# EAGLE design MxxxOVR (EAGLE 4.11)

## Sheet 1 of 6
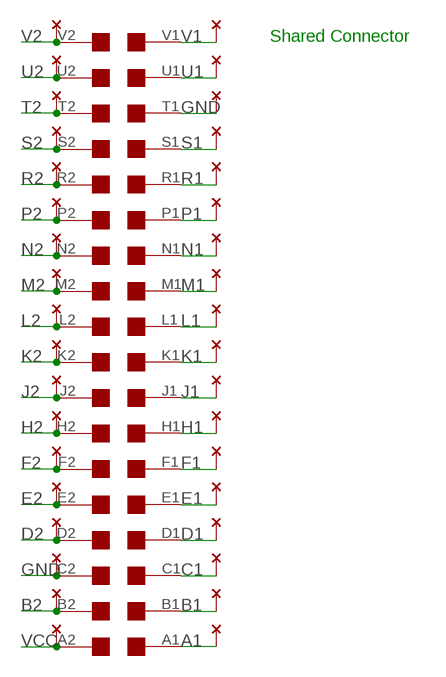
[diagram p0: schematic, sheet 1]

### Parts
U$1  EDGE-2  [EDGE-CON2]
U$4  THRU-HOLE2  [THRU-HOLEB]

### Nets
A1: U$1.A1 U$4.A2 ; also sheet 2,3,4,5,6
B1: U$1.B1 U$4.B2 ; also sheet 2,3,4,5,6
B2: U$1.B2 U$4.B1
C1: U$1.C1 U$4.C2 ; also sheet 2,3,4,5,6
D1: U$1.D1 U$4.D2 ; also sheet 2,3,4,5,6
D2: U$1.D2 U$4.D1 ; also sheet 2,3,4,5,6
E1: U$1.E1 U$4.E2 ; also sheet 2,3,4,5
E2: U$1.E2 U$4.E1 ; also sheet 2,3,4,5,6
F1: U$1.F1 U$4.F2 ; also sheet 2,3,4,5,6
F2: U$1.F2 U$4.F1 ; also sheet 2,3,4,5,6
GND [Power]: U$1.C2 U$1.T1 U$4.C1 U$4.T2 ; also sheet 2,3,4,5,6
H1: U$1.H1 U$4.H2 ; also sheet 2,3,4,5,6
H2: U$1.H2 U$4.H1 ; also sheet 2,3,4,5,6
J1: U$1.J1 U$4.J2 ; also sheet 2,3,4,5,6
J2: U$1.J2 U$4.J1 ; also sheet 2,3,4,5,6
K1: U$1.K1 U$4.K2 ; also sheet 2,3,4,5,6
K2: U$1.K2 U$4.K1 ; also sheet 2,3,4,5,6
L1: U$1.L1 U$4.L2 ; also sheet 2,3,4,5
L2: U$1.L2 U$4.L1 ; also sheet 2,3,4,5,6
M1: U$1.M1 U$4.M2 ; also sheet 2,3,4,5,6
M2: U$1.M2 U$4.M1 ; also sheet 2,3,4,5,6
N1: U$1.N1 U$4.N2 ; also sheet 2,3,4,5,6
N2: U$1.N2 U$4.N1 ; also sheet 2,3,4,5,6
P1: U$1.P1 U$4.P2 ; also sheet 2,3,4,5,6
P2: U$1.P2 U$4.P1 ; also sheet 2,3,4,5,6
R1: U$1.R1 U$4.R2 ; also sheet 2,3,4,5,6
R2: U$1.R2 U$4.R1 ; also sheet 2,3,4,5,6
S1: U$1.S1 U$4.S2 ; also sheet 2,3,4,5
S2: U$1.S2 U$4.S1 ; also sheet 2,3,4,5,6
T2: U$1.T2 U$4.T1 ; also sheet 2,3,4,5,6
U1: U$1.U1 U$4.U2 ; also sheet 2,3,4
U2: U$1.U2 U$4.U1 ; also sheet 2,3,4,5,6
V1: U$1.V1 U$4.V2 ; also sheet 2,3,4
V2: U$1.V2 U$4.V1 ; also sheet 2,3,4,5,6
VCC [Power]: U$1.A2 U$4.A1 ; also sheet 2,3,4,5,6

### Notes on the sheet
- Shared Connector

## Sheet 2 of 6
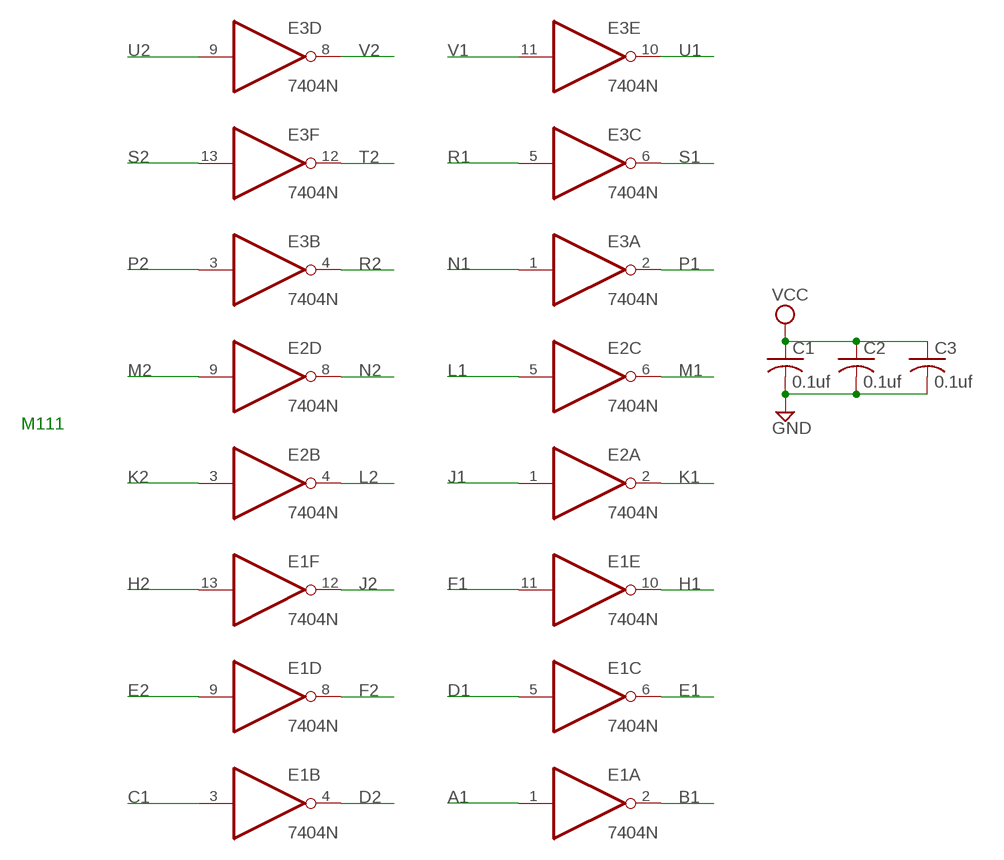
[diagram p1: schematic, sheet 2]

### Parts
C1  0.1uf  C-US050-025X075  [C050-025X075]
C2  0.1uf  C-US050-025X075  [C050-025X075]
C3  0.1uf  C-US050-025X075  [C050-025X075]
E1  7404N  [DIL14]
E2  7404N  [DIL14]
E3  7404N  [DIL14]

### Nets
A1: E1.1(A:I) ; also sheet 1,3,4,5,6
B1: E1.2(A:O) ; also sheet 1,3,4,5,6
C1: E1.3(B:I) ; also sheet 1,3,4,5,6
D1: E1.5(C:I) ; also sheet 1,3,4,5,6
D2: E1.4(B:O) ; also sheet 1,3,4,5,6
E1: E1.6(C:O) ; also sheet 1,3,4,5
E2: E1.9(D:I) ; also sheet 1,3,4,5,6
F1: E1.11(E:I) ; also sheet 1,3,4,5,6
F2: E1.8(D:O) ; also sheet 1,3,4,5,6
GND [Power]: C1.2 C2.2 C3.2 ; also sheet 1,3,4,5,6
H1: E1.10(E:O) ; also sheet 1,3,4,5,6
H2: E1.13(F:I) ; also sheet 1,3,4,5,6
J1: E2.1(A:I) ; also sheet 1,3,4,5,6
J2: E1.12(F:O) ; also sheet 1,3,4,5,6
K1: E2.2(A:O) ; also sheet 1,3,4,5,6
K2: E2.3(B:I) ; also sheet 1,3,4,5,6
L1: E2.5(C:I) ; also sheet 1,3,4,5
L2: E2.4(B:O) ; also sheet 1,3,4,5,6
M1: E2.6(C:O) ; also sheet 1,3,4,5,6
M2: E2.9(D:I) ; also sheet 1,3,4,5,6
N1: E3.1(A:I) ; also sheet 1,3,4,5,6
N2: E2.8(D:O) ; also sheet 1,3,4,5,6
P1: E3.2(A:O) ; also sheet 1,3,4,5,6
P2: E3.3(B:I) ; also sheet 1,3,4,5,6
R1: E3.5(C:I) ; also sheet 1,3,4,5,6
R2: E3.4(B:O) ; also sheet 1,3,4,5,6
S1: E3.6(C:O) ; also sheet 1,3,4,5
S2: E3.13(F:I) ; also sheet 1,3,4,5,6
T2: E3.12(F:O) ; also sheet 1,3,4,5,6
U1: E3.10(E:O) ; also sheet 1,3,4
U2: E3.9(D:I) ; also sheet 1,3,4,5,6
V1: E3.11(E:I) ; also sheet 1,3,4
V2: E3.8(D:O) ; also sheet 1,3,4,5,6
VCC [Power]: C1.1 C2.1 C3.1 ; also sheet 1,3,4,5,6
Unconnected: E2.10(E:O) E2.11(E:I) E2.12(F:O) E2.13(F:I)

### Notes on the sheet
- M111

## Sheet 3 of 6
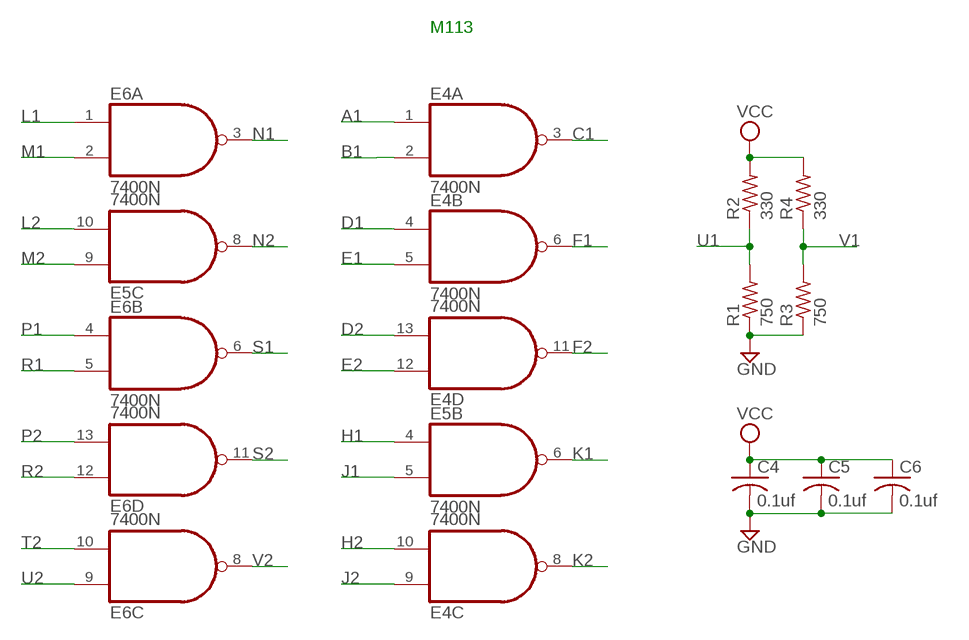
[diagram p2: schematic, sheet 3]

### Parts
C4  0.1uf  C-US050-025X075  [C050-025X075]
C5  0.1uf  C-US050-025X075  [C050-025X075]
C6  0.1uf  C-US050-025X075  [C050-025X075]
E4  7400N  [DIL14]
E5  7400N  [DIL14]
E6  7400N  [DIL14]
R1  750  R-US_0207/10  [0207/10]
R2  330  R-US_0207/10  [0207/10]
R3  750  R-US_0207/10  [0207/10]
R4  330  R-US_0207/10  [0207/10]

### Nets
A1: E4.1(A:I0) ; also sheet 1,2,4,5,6
B1: E4.2(A:I1) ; also sheet 1,2,4,5,6
C1: E4.3(A:O) ; also sheet 1,2,4,5,6
D1: E4.4(B:I0) ; also sheet 1,2,4,5,6
D2: E4.13(D:I1) ; also sheet 1,2,4,5,6
E1: E4.5(B:I1) ; also sheet 1,2,4,5
E2: E4.12(D:I0) ; also sheet 1,2,4,5,6
F1: E4.6(B:O) ; also sheet 1,2,4,5,6
F2: E4.11(D:O) ; also sheet 1,2,4,5,6
GND [Power]: C4.2 C5.2 C6.2 R1.1 R3.1 ; also sheet 1,2,4,5,6
H1: E5.4(B:I0) ; also sheet 1,2,4,5,6
H2: E4.10(C:I1) ; also sheet 1,2,4,5,6
J1: E5.5(B:I1) ; also sheet 1,2,4,5,6
J2: E4.9(C:I0) ; also sheet 1,2,4,5,6
K1: E5.6(B:O) ; also sheet 1,2,4,5,6
K2: E4.8(C:O) ; also sheet 1,2,4,5,6
L1: E6.1(A:I0) ; also sheet 1,2,4,5
L2: E5.10(C:I1) ; also sheet 1,2,4,5,6
M1: E6.2(A:I1) ; also sheet 1,2,4,5,6
M2: E5.9(C:I0) ; also sheet 1,2,4,5,6
N1: E6.3(A:O) ; also sheet 1,2,4,5,6
N2: E5.8(C:O) ; also sheet 1,2,4,5,6
P1: E6.4(B:I0) ; also sheet 1,2,4,5,6
P2: E6.13(D:I1) ; also sheet 1,2,4,5,6
R1: E6.5(B:I1) ; also sheet 1,2,4,5,6
R2: E6.12(D:I0) ; also sheet 1,2,4,5,6
S1: E6.6(B:O) ; also sheet 1,2,4,5
S2: E6.11(D:O) ; also sheet 1,2,4,5,6
T2: E6.10(C:I1) ; also sheet 1,2,4,5,6
U1: R1.2 R2.1 ; also sheet 1,2,4
U2: E6.9(C:I0) ; also sheet 1,2,4,5,6
V1: R3.2 R4.1 ; also sheet 1,2,4
V2: E6.8(C:O) ; also sheet 1,2,4,5,6
VCC [Power]: C4.1 C5.1 C6.1 R2.2 R4.2 ; also sheet 1,2,4,5,6
Unconnected: E5.1(A:I0) E5.2(A:I1) E5.3(A:O) E5.11(D:O) E5.12(D:I0) E5.13(D:I1)

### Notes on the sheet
- M113

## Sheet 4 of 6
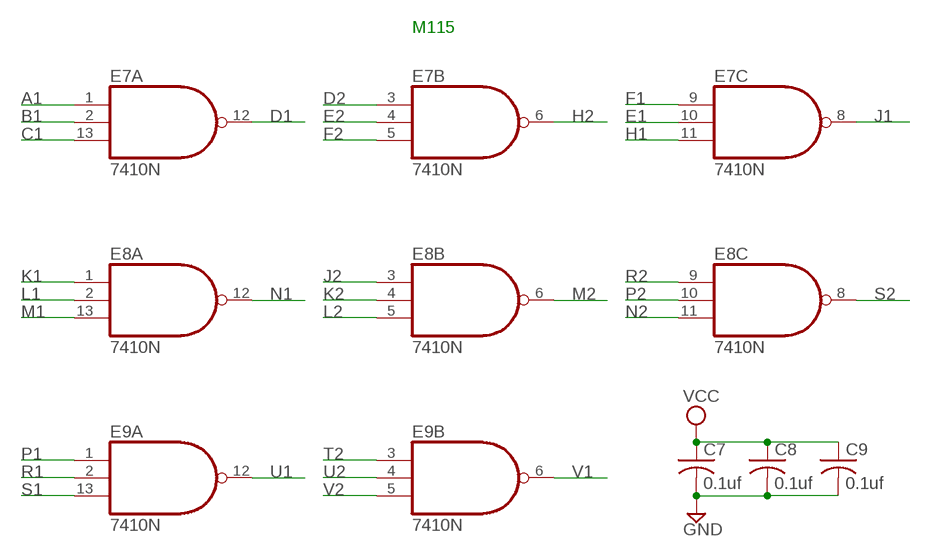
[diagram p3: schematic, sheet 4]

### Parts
C7  0.1uf  C-US050-025X075  [C050-025X075]
C8  0.1uf  C-US050-025X075  [C050-025X075]
C9  0.1uf  C-US050-025X075  [C050-025X075]
E7  7410N  [DIL14]
E8  7410N  [DIL14]
E9  7410N  [DIL14]

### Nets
A1: E7.1(A:I0) ; also sheet 1,2,3,5,6
B1: E7.2(A:I1) ; also sheet 1,2,3,5,6
C1: E7.13(A:I2) ; also sheet 1,2,3,5,6
D1: E7.12(A:O) ; also sheet 1,2,3,5,6
D2: E7.3(B:I0) ; also sheet 1,2,3,5,6
E1: E7.10(C:I1) ; also sheet 1,2,3,5
E2: E7.4(B:I1) ; also sheet 1,2,3,5,6
F1: E7.9(C:I0) ; also sheet 1,2,3,5,6
F2: E7.5(B:I2) ; also sheet 1,2,3,5,6
GND [Power]: C7.2 C8.2 C9.2 ; also sheet 1,2,3,5,6
H1: E7.11(C:I2) ; also sheet 1,2,3,5,6
H2: E7.6(B:O) ; also sheet 1,2,3,5,6
J1: E7.8(C:O) ; also sheet 1,2,3,5,6
J2: E8.3(B:I0) ; also sheet 1,2,3,5,6
K1: E8.1(A:I0) ; also sheet 1,2,3,5,6
K2: E8.4(B:I1) ; also sheet 1,2,3,5,6
L1: E8.2(A:I1) ; also sheet 1,2,3,5
L2: E8.5(B:I2) ; also sheet 1,2,3,5,6
M1: E8.13(A:I2) ; also sheet 1,2,3,5,6
M2: E8.6(B:O) ; also sheet 1,2,3,5,6
N1: E8.12(A:O) ; also sheet 1,2,3,5,6
N2: E8.11(C:I2) ; also sheet 1,2,3,5,6
P1: E9.1(A:I0) ; also sheet 1,2,3,5,6
P2: E8.10(C:I1) ; also sheet 1,2,3,5,6
R1: E9.2(A:I1) ; also sheet 1,2,3,5,6
R2: E8.9(C:I0) ; also sheet 1,2,3,5,6
S1: E9.13(A:I2) ; also sheet 1,2,3,5
S2: E8.8(C:O) ; also sheet 1,2,3,5,6
T2: E9.3(B:I0) ; also sheet 1,2,3,5,6
U1: E9.12(A:O) ; also sheet 1,2,3
U2: E9.4(B:I1) ; also sheet 1,2,3,5,6
V1: E9.6(B:O) ; also sheet 1,2,3
V2: E9.5(B:I2) ; also sheet 1,2,3,5,6
VCC [Power]: C7.1 C8.1 C9.1 ; also sheet 1,2,3,5,6
Unconnected: E9.8(C:O) E9.9(C:I0) E9.10(C:I1) E9.11(C:I2)

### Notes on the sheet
- M115

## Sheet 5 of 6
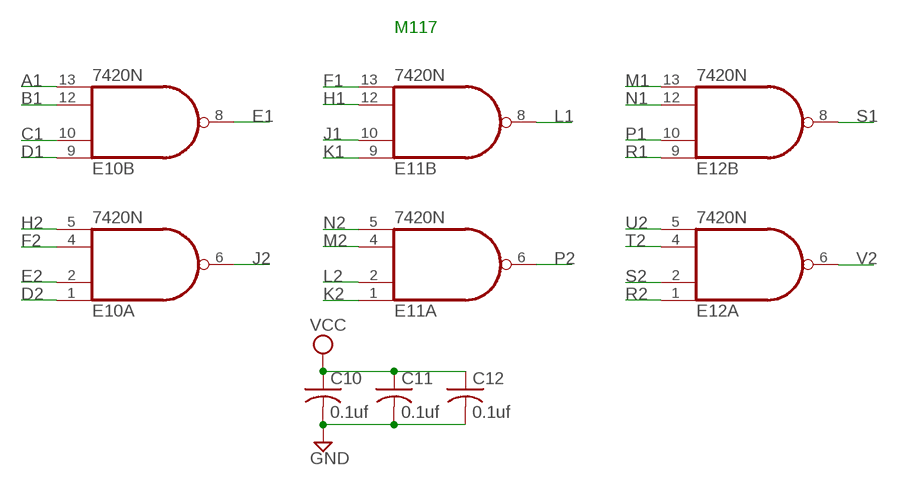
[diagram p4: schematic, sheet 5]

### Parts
C10  0.1uf  C-US050-025X075  [C050-025X075]
C11  0.1uf  C-US050-025X075  [C050-025X075]
C12  0.1uf  C-US050-025X075  [C050-025X075]
E10  7420N  74S20N  [DIL14]
E11  7420N  74S20N  [DIL14]
E12  7420N  74S20N  [DIL14]

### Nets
A1: E10.13(B:I3) ; also sheet 1,2,3,4,6
B1: E10.12(B:I2) ; also sheet 1,2,3,4,6
C1: E10.10(B:I1) ; also sheet 1,2,3,4,6
D1: E10.9(B:I0) ; also sheet 1,2,3,4,6
D2: E10.1(A:I0) ; also sheet 1,2,3,4,6
E1: E10.8(B:O) ; also sheet 1,2,3,4
E2: E10.2(A:I1) ; also sheet 1,2,3,4,6
F1: E11.13(B:I3) ; also sheet 1,2,3,4,6
F2: E10.4(A:I2) ; also sheet 1,2,3,4,6
GND [Power]: C10.2 C11.2 C12.2 ; also sheet 1,2,3,4,6
H1: E11.12(B:I2) ; also sheet 1,2,3,4,6
H2: E10.5(A:I3) ; also sheet 1,2,3,4,6
J1: E11.10(B:I1) ; also sheet 1,2,3,4,6
J2: E10.6(A:O) ; also sheet 1,2,3,4,6
K1: E11.9(B:I0) ; also sheet 1,2,3,4,6
K2: E11.1(A:I0) ; also sheet 1,2,3,4,6
L1: E11.8(B:O) ; also sheet 1,2,3,4
L2: E11.2(A:I1) ; also sheet 1,2,3,4,6
M1: E12.13(B:I3) ; also sheet 1,2,3,4,6
M2: E11.4(A:I2) ; also sheet 1,2,3,4,6
N1: E12.12(B:I2) ; also sheet 1,2,3,4,6
N2: E11.5(A:I3) ; also sheet 1,2,3,4,6
P1: E12.10(B:I1) ; also sheet 1,2,3,4,6
P2: E11.6(A:O) ; also sheet 1,2,3,4,6
R1: E12.9(B:I0) ; also sheet 1,2,3,4,6
R2: E12.1(A:I0) ; also sheet 1,2,3,4,6
S1: E12.8(B:O) ; also sheet 1,2,3,4
S2: E12.2(A:I1) ; also sheet 1,2,3,4,6
T2: E12.4(A:I2) ; also sheet 1,2,3,4,6
U2: E12.5(A:I3) ; also sheet 1,2,3,4,6
V2: E12.6(A:O) ; also sheet 1,2,3,4,6
VCC [Power]: C10.1 C11.1 C12.1 ; also sheet 1,2,3,4,6

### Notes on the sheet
- M117

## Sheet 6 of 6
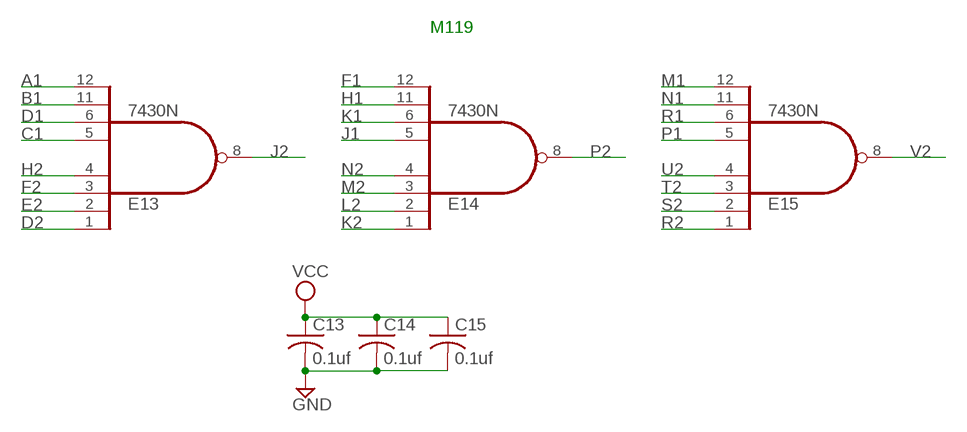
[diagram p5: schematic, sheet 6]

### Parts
C13  0.1uf  C-US050-025X075  [C050-025X075]
C14  0.1uf  C-US050-025X075  [C050-025X075]
C15  0.1uf  C-US050-025X075  [C050-025X075]
E13  7430N  [DIL14]
E14  7430N  [DIL14]
E15  7430N  [DIL14]

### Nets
A1: E13.12(I7) ; also sheet 1,2,3,4,5
B1: E13.11(I6) ; also sheet 1,2,3,4,5
C1: E13.5(I4) ; also sheet 1,2,3,4,5
D1: E13.6(I5) ; also sheet 1,2,3,4,5
D2: E13.1(I0) ; also sheet 1,2,3,4,5
E2: E13.2(I1) ; also sheet 1,2,3,4,5
F1: E14.12(I7) ; also sheet 1,2,3,4,5
F2: E13.3(I2) ; also sheet 1,2,3,4,5
GND [Power]: C13.2 C14.2 C15.2 ; also sheet 1,2,3,4,5
H1: E14.11(I6) ; also sheet 1,2,3,4,5
H2: E13.4(I3) ; also sheet 1,2,3,4,5
J1: E14.5(I4) ; also sheet 1,2,3,4,5
J2: E13.8(O) ; also sheet 1,2,3,4,5
K1: E14.6(I5) ; also sheet 1,2,3,4,5
K2: E14.1(I0) ; also sheet 1,2,3,4,5
L2: E14.2(I1) ; also sheet 1,2,3,4,5
M1: E15.12(I7) ; also sheet 1,2,3,4,5
M2: E14.3(I2) ; also sheet 1,2,3,4,5
N1: E15.11(I6) ; also sheet 1,2,3,4,5
N2: E14.4(I3) ; also sheet 1,2,3,4,5
P1: E15.5(I4) ; also sheet 1,2,3,4,5
P2: E14.8(O) ; also sheet 1,2,3,4,5
R1: E15.6(I5) ; also sheet 1,2,3,4,5
R2: E15.1(I0) ; also sheet 1,2,3,4,5
S2: E15.2(I1) ; also sheet 1,2,3,4,5
T2: E15.3(I2) ; also sheet 1,2,3,4,5
U2: E15.4(I3) ; also sheet 1,2,3,4,5
V2: E15.8(O) ; also sheet 1,2,3,4,5
VCC [Power]: C13.1 C14.1 C15.1 ; also sheet 1,2,3,4,5

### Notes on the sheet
- M119

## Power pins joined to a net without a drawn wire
GND: E1.7(P:GND) E2.7(P:GND) E3.7(P:GND) E4.7(P:GND) E5.7(P:GND) E6.7(P:GND) E7.7(P:GND) E8.7(P:GND) E9.7(P:GND) E10.7(P:GND) E11.7(P:GND) E12.7(P:GND) E13.7(GND) E14.7(GND) E15.7(GND)
VCC: E1.14(P:VCC) E2.14(P:VCC) E3.14(P:VCC) E4.14(P:VCC) E5.14(P:VCC) E6.14(P:VCC) E7.14(P:VCC) E8.14(P:VCC) E9.14(P:VCC) E10.14(P:VCC) E11.14(P:VCC) E12.14(P:VCC) E13.14(VCC) E14.14(VCC) E15.14(VCC)

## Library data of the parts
C1-C15 = rcl:C-US: CAPACITOR, American symbol
E1-E3 = 74xx-us:74*04: Hex INVERTER
E4-E6 = 74xx-us:74*00: Quad 2-input NAND gate
E7-E9 = 74xx-us:74*10: Triple 3-input NAND gate
E10-E12 = 74xx-us:74*20: Dual 4-input NAND gate
E13-E15 = 74xx-us:74*30: 8-input NAND gate
R1-R4 = rcl:R-US_: RESISTOR, American symbol
U$1 = dec-con:EDGE-2: Double-Sided DEC edge connector.
U$4 = dec-con:THRU-HOLE2: Thru-Hole addition to double-sided edge connector.

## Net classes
1 Power: width 0.381 mm

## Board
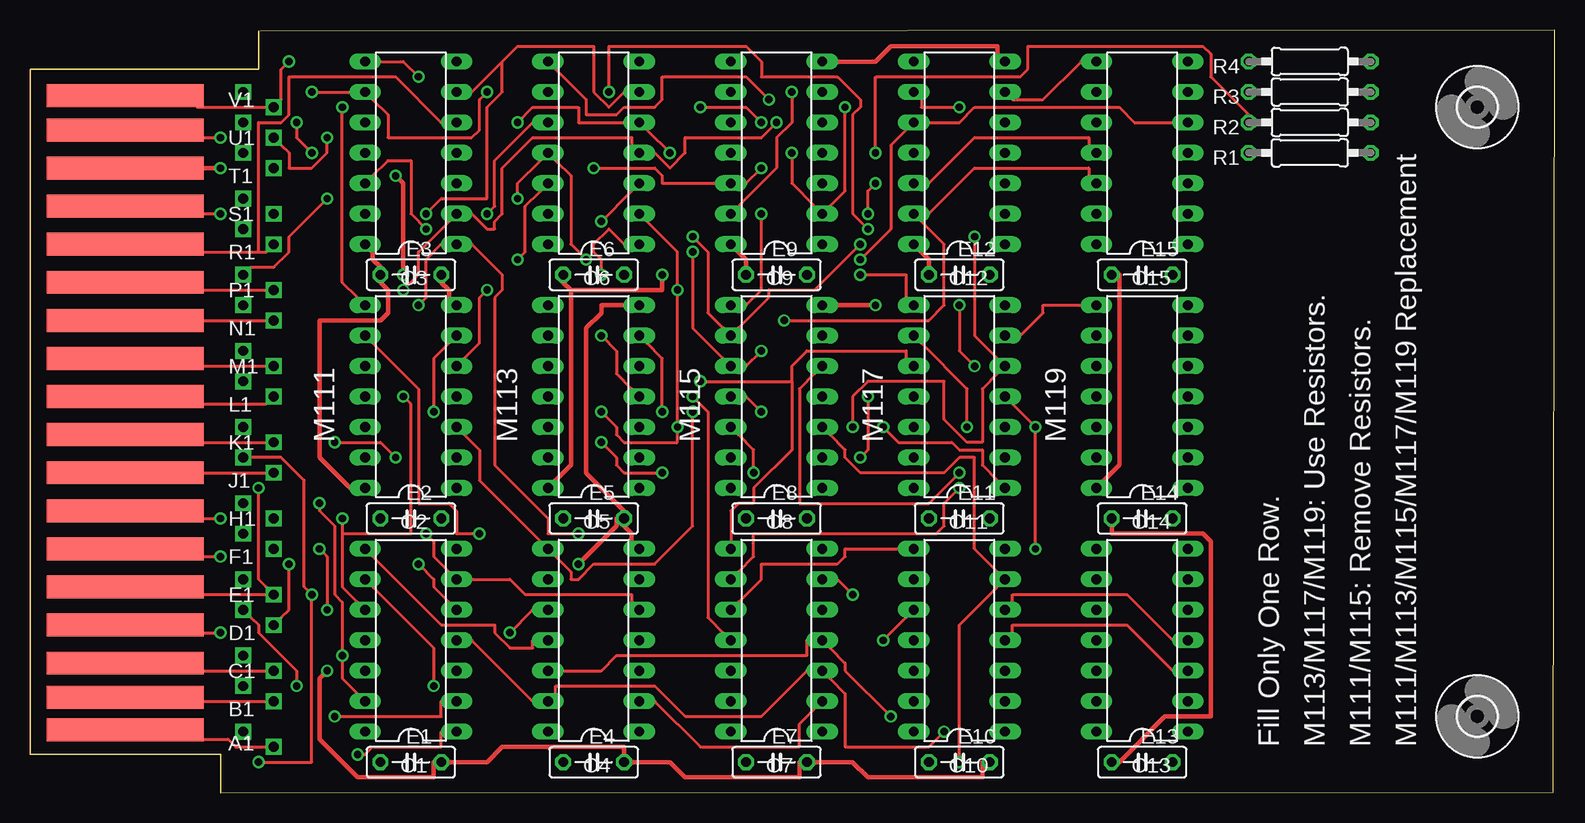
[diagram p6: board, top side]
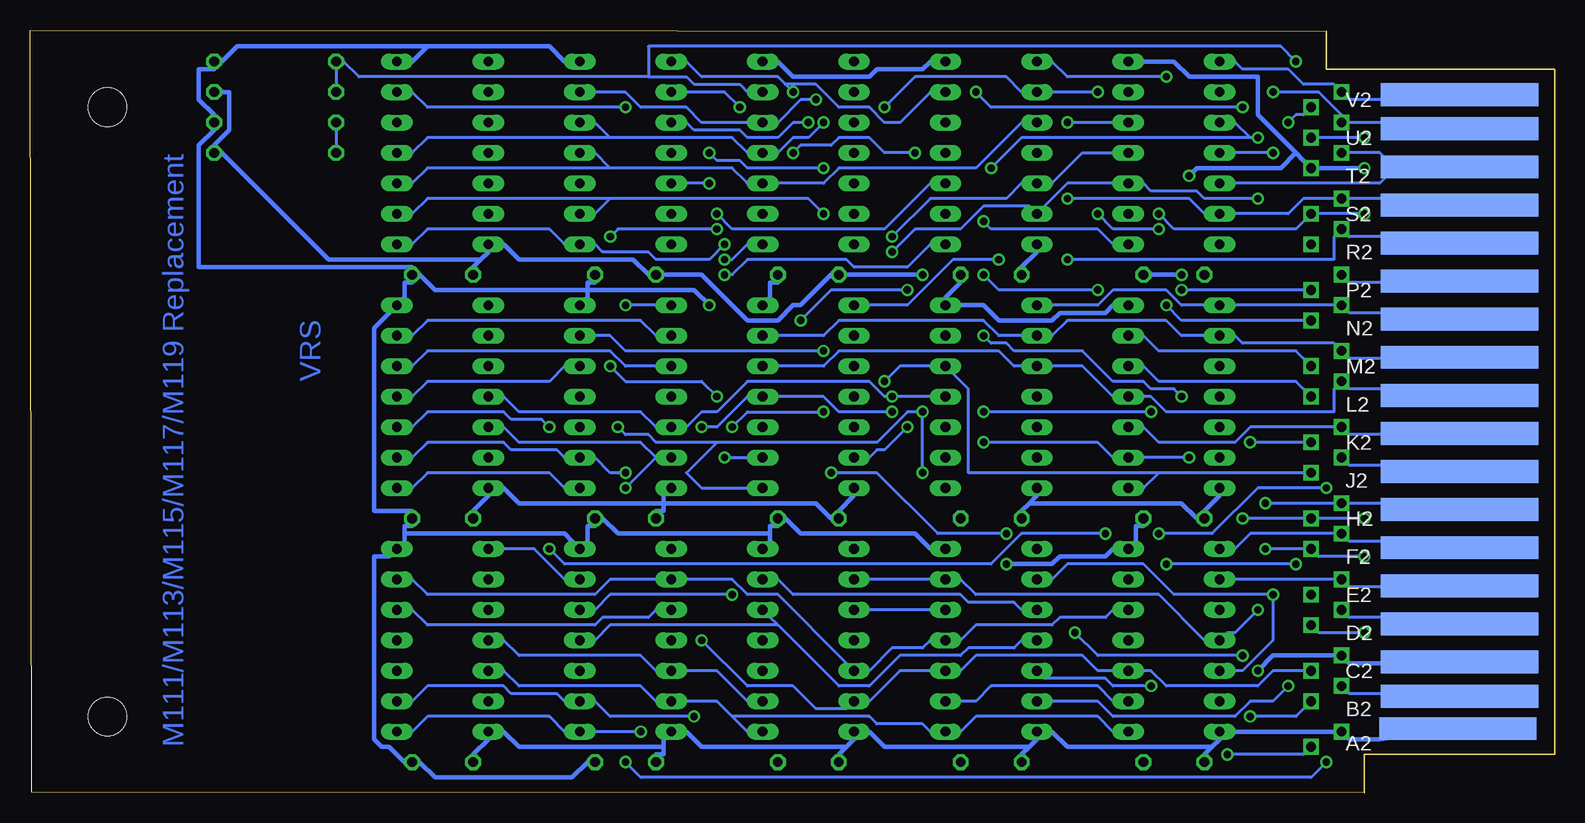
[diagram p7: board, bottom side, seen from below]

Size 127.11 x 63.59 mm. Coordinates in mm from the lower left corner, seen from the top.
Outline: 15.88,0 126.98,0.04 127.11,63.59 19.18,63.5
Copper layers (1*16): Top 0.035mm / dielectric 1.5mm / Bottom 0.035mm
Design rules "olimex10mil": minimum track width 10mil, minimum drill 24mil, track to track 10mil, track to pad 10mil, pad to pad 10mil, via to via 10mil, smd to smd 10mil, copper to edge 40mil, drill to drill 10mil, minimum pad ring 10mil, minimum via ring 8mil, stop-mask expansion 0mil, vias tented up to drill 0mil, thermal gap 10mil

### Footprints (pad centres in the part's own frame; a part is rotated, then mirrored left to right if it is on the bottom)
C050-025X075 = drill 0.813 octagon: 1 -2.54,0; 2 2.54,0
DIL14 = drill 0.813 long: 1 -7.62,-3.81; 2 -5.08,-3.81; 3 -2.54,-3.81; 4 0,-3.81; 5 2.54,-3.81; 6 5.08,-3.81; 7 7.62,-3.81; 8 7.62,3.81; 9 5.08,3.81; 10 2.54,3.81; 11 0,3.81; 12 -2.54,3.81; 13 -5.08,3.81; 14 -7.62,3.81
0207/10 = drill 0.813 octagon: 1 -5.08,0; 2 5.08,0
EDGE-CON2 = smd 13.106 x 1.905: A1 7.938,5.239; B1 7.938,7.938; C1 7.938,10.795; D1 7.938,13.97; E1 7.938,17.145; F1 7.938,20.32; H1 7.938,23.495; J1 7.938,26.67; K1 7.938,29.845; L1 7.938,33.02; M1 7.938,36.195; N1 7.938,39.37; P1 7.938,42.545; R1 7.938,45.72; S1 7.938,48.895; T1 7.938,52.07; U1 7.938,55.245; V1 7.938,58.102 | smd 13.106 x 1.905 bottom: A2 8.096,5.34; B2 7.938,8.039; C2 7.938,10.897; D2 7.938,14.072; E2 7.938,17.247; F2 7.938,20.422; H2 7.938,23.597; J2 7.938,26.772; K2 7.938,29.947; L2 7.938,33.122; M2 7.938,36.297; N2 7.938,39.472; P2 7.938,42.647; R2 7.938,45.822; S2 7.938,48.997; T2 7.938,52.172; U2 7.938,55.347; V2 7.938,58.204
3,2 = hole 3.2: 0,0
THRU-HOLEB = drill 0.813 square: A1 17.78,5.08; A2 20.32,3.81; B1 17.78,8.89; B2 20.32,7.62; C1 17.78,11.43; C2 20.32,10.16; D1 17.78,15.24; D2 20.32,13.97; E1 17.78,17.78; E2 20.32,16.51; F1 17.78,21.59; F2 20.32,20.32; H1 17.78,24.13; H2 20.32,22.86; J1 17.78,27.94; J2 20.32,26.67; K1 17.78,30.48; K2 20.32,29.21; L1 17.78,34.29; L2 20.32,33.02; M1 17.78,36.83; M2 20.32,35.56; N1 17.78,40.64; N2 20.32,39.37; P1 17.78,43.18; P2 20.32,41.91; R1 17.78,46.99; R2 20.32,45.72; S1 17.78,49.53; S2 20.32,48.26; T1 17.78,53.34; T2 20.32,52.07; U1 17.78,55.88; U2 20.32,54.61; V1 17.78,58.42; V2 20.32,57.15

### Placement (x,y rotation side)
C1  31.75,2.54 0 top
C2  31.75,22.86 0 top
C3  31.75,43.18 0 top
C4  46.99,2.54 0 top
C5  46.99,22.86 0 top
C6  46.99,43.18 0 top
C7  62.23,2.54 0 top
C8  62.23,22.86 0 top
C9  62.23,43.18 0 top
C10  77.47,2.54 0 top
C11  77.47,22.86 0 top
C12  77.47,43.18 0 top
C13  92.71,2.54 0 top
C14  92.71,22.86 0 top
C15  92.71,43.18 0 top
E1  31.75,12.7 90 top
E2  31.75,33.02 90 top
E3  31.75,53.34 90 top
E4  46.99,12.7 90 top
E5  46.99,33.02 90 top
E6  46.99,53.34 90 top
E7  62.23,12.7 90 top
E8  62.23,33.02 90 top
E9  62.23,53.34 90 top
E10  77.47,12.7 90 top
E11  77.47,33.02 90 top
E12  77.47,53.34 90 top
E13  92.71,12.7 90 top
E14  92.71,33.02 90 top
E15  92.71,53.34 90 top
R1  106.68,55.88 180 top
R2  106.68,53.34 0 top
R3  106.68,60.96 180 top
R4  106.68,58.42 0 top
U$1  0,0 0 top
U$2  [3,2]  120.65,6.35 0 top
U$3  [3,2]  120.65,57.15 0 top
U$4  0,0 0 top

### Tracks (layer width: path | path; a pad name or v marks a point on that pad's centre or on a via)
A1  (via drill 0.61)
  Top 0.254: U$4.A2 19.68,3.81 17.14,3.81 16.51,4.45 13.97,4.45 U$1.A1 | v27.3,3.17 27.94,3.17 28.57,3.81 34.29,3.81 34.29,5.08 E1.1
  Bottom 0.254: E1.1 36.83,5.08 38.1,6.35 48.26,6.35 49.53,5.08 E4.1 52.07,5.08 52.7,5.71 56.52,5.71 57.15,6.35 68.58,6.35 | 68.58,6.35 69.85,7.62 72.39,7.62 E10.13 74.93,7.62 76.2,8.89 86.36,8.89 87.63,10.16 E13.12 | 68.58,6.35 67.31,5.08 E7.1 | v27.3,3.17 20.95,3.17 U$4.A2
B1  (via drill 0.61)
  Top 0.254: U$4.B2 19.68,7.62 13.97,7.62 U$1.B1 | E4.2 52.07,7.62 55.88,3.81 64.14,3.81 64.14,5.71 65.41,6.99 E7.2 | v25.4,6.35 34.29,6.35 34.29,7.62 E1.2
  Bottom 0.254: E1.2 36.83,7.62 38.1,8.89 46.99,8.89 48.26,7.62 49.53,7.62 E4.2 | E7.2 67.31,7.62 69.85,10.16 72.39,10.16 E10.12 74.93,10.16 76.2,11.43 86.36,11.43 87.63,12.7 E13.11 | v25.4,6.35 21.59,6.35 20.95,6.99 U$4.B2
B2
  Bottom 0.254: U$4.B1 17.14,8.26 13.97,8.26 U$1.B2
C1  (via drill 0.61)
  Top 0.254: v71.12,12.7 73.03,14.61 E10.10 | U$1.C1 13.97,10.16 19.68,10.16 U$4.C2
  Bottom 0.254: E10.10 74.93,15.24 75.56,14.61 79.38,14.61 80.01,13.97 93.98,13.97 95.25,15.24 E13.5 | U$4.C2 20.95,10.16 23.5,10.16 24.77,8.89 32.38,8.89 33.66,10.16 34.29,10.16 E1.3 36.83,10.16 38.1,10.16 39.37,11.43 48.26,11.43 49.53,10.16 E4.3 52.07,10.16 54.61,10.16 57.15,7.62 E7.13 59.05,6.99 61.59,6.99 63.5,8.89 67.31,8.89 v71.12,12.7
D1  (via drill 0.61)
  Top 0.254: v15.88,13.34 13.97,13.34 U$1.D1 | v21.59,19.05 21.59,15.24 20.95,14.61 U$4.D2 | v32.38,19.05 33.66,17.78 33.66,17.14 34.92,15.88 E1.5
  Bottom 0.254: v15.88,13.34 19.68,13.34 U$4.D2 | E1.5 36.83,15.24 37.47,14.61 41.27,14.61 41.91,13.97 48.26,13.97 49.53,12.7 E4.4 52.07,12.7 52.7,12.06 55.24,12.06 57.15,10.16 E7.12 59.05,10.79 64.77,16.51 67.31,16.51 68.58,17.78 72.39,17.78 E10.9 74.93,17.78 78.74,17.78 80.01,16.51 93.98,16.51 95.25,17.78 E13.6 | v21.59,19.05 v32.38,19.05
D2  (via drill 0.61)
  Top 0.254: E1.4 36.83,12.7 41.91,7.62 E4.13 43.81,8.26 43.81,8.89 52.07,8.89 54.61,6.35 60.96,6.35 64.77,10.16 E7.3 66.67,9.53 67.94,8.26 67.94,3.81 74.93,3.81 v76.2,5.08 | v22.23,8.89 22.23,10.16 19.05,13.34 19.05,13.97 18.41,14.61 U$4.D1
  Bottom 0.254: U$4.D1 17.14,14.61 13.97,14.61 U$1.D2 | E13.1 95.25,5.08 93.98,6.35 83.82,6.35 82.55,5.08 E10.1 80.01,5.08 v76.2,5.08 | v22.23,8.89 23.5,7.62 25.4,7.62 26.67,6.35 36.83,6.35 38.1,7.62 41.91,7.62 E4.13
E1  (via drill 0.61)
  Top 0.254: U$1.E1 13.97,16.51 19.68,16.51 U$4.E2 19.68,17.14 19.05,17.78 v19.05,25.4 | E4.5 50.16,15.88 50.16,16.51 41.27,16.51 40.01,17.78 36.83,17.78 E1.6 34.92,18.41 33.66,19.68 33.66,20.95 v33.02,21.59 | E10.8 72.39,20.32 67.94,20.32 67.94,19.68 67.31,19.05 60.96,19.05 60.96,17.78 59.05,15.88 E7.10
  Bottom 0.254: E4.5 52.07,15.24 57.15,15.24 E7.10 | v19.05,25.4 24.77,25.4 28.57,21.59 v33.02,21.59
E2  (via drill 0.61)
  Top 0.254: E4.12 44.45,10.16 47.62,10.16 48.9,11.43 64.77,11.43 64.77,12.7 E7.4 66.67,12.06 67.94,10.79 67.94,10.16 v71.75,6.35 | v33.66,8.89 33.66,12.06 28.57,17.14 E1.9
  Bottom 0.254: U$1.E2 13.97,17.14 17.14,17.14 U$4.E1 18.41,17.78 26.67,17.78 E1.9 | E13.2 95.25,7.62 93.98,8.89 87.63,8.89 87,8.26 83.19,8.26 82.55,7.62 E10.2 80.01,7.62 78.74,6.35 v71.75,6.35 | v33.66,8.89 36.83,8.89 37.47,9.53 42.55,9.53 E4.12
F1  (via drill 0.61)
  Top 0.254: v15.88,19.68 13.97,19.68 U$1.F1 | v77.47,25.4 76.2,24.13 76.2,22.23 75.56,21.59 60.33,21.59 60.33,19.68 59.05,18.41 E7.9 | v24.13,20.32 24.77,19.68 v24.77,15.24
  Bottom 0.254: v15.88,19.68 19.68,19.68 U$4.F2 20.95,20.32 v24.13,20.32 | 74.93,27.94 76.2,29.21 86.36,29.21 87.63,30.48 E14.12 | 74.93,27.94 E11.13 74.93,27.94 | E7.9 57.15,17.78 52.07,17.78 E4.6 49.53,17.78 48.26,16.51 33.02,16.51 29.21,12.7 E1.11 27.3,13.34 26.67,13.34 v24.77,15.24 | v77.47,25.4 74.93,27.94
F2
  Top 0.254: E13.3 95.25,10.16 91.44,13.97 81.92,13.97 81.92,13.34 E10.4 | E1.8 28.57,19.68 34.29,13.97 38.73,13.97 38.73,13.34 40.01,12.06 41.91,12.06 41.91,12.7 E4.11
  Bottom 0.254: U$1.F2 13.97,20.95 17.14,20.95 U$4.F1 18.41,21.59 25.4,21.59 26.67,20.32 E1.8 | 64.77,13.97 65.41,14.61 E7.5 | 64.77,13.97 59.69,8.89 57.15,8.89 54.61,11.43 49.53,11.43 48.9,12.06 45.09,12.06 44.45,12.7 E4.11 | 64.77,13.97 78.74,13.97 80.01,12.7 E10.4
GND  (via drill 0.61)
  Top 0.381: C10.2 79.38,2.54 79.38,1.27 69.85,1.27 68.58,2.54 65.41,2.54 C7.2 64.14,2.54 64.14,1.27 54.61,1.27 53.34,2.54 50.16,2.54 C4.2 49.53,3.17 49.53,3.81 39.37,3.81 38.1,2.54 34.92,2.54 C1.2 33.66,2.54 33.66,1.27 27.3,1.27 24.13,4.45 24.13,9.53 v24.77,10.16 | E9.7 67.31,60.96 70.48,60.96 71.75,62.23 80.64,62.23 80.64,61.59 E12.7 | v15.88,52.07 13.97,52.07 U$1.T1 | v70.48,40.64 67.31,40.64 E8.7 | C3.2 34.29,42.55 34.92,41.91 34.92,41.27 E2.7 | C5.2 49.53,22.23 50.16,21.59 50.16,20.95 E4.7 | v45.72,19.05 48.9,22.23 48.9,22.86 C5.2 | E5.7 49.53,40.64 47.62,40.64 47.62,40.01 46.35,38.73 46.35,26.67 49.53,23.5 C5.2 | v30.48,51.44 31.11,50.8 v31.11,43.18
  Bottom 0.381: U$1.C2 13.97,10.79 17.14,10.79 U$4.C1 18.41,11.43 23.5,11.43 v24.77,10.16 | C10.2 80.64,2.54 81.92,1.27 93.34,1.27 94.61,2.54 C13.2 95.89,2.54 97.16,3.81 97.79,3.81 98.42,4.45 98.42,19.68 97.16,19.68 E13.7 95.89,20.95 95.89,21.59 | E6.7 52.07,60.96 52.7,60.33 56.52,60.33 57.15,59.69 63.5,59.69 64.77,60.96 E9.7 | 93.98,62.23 83.82,62.23 82.55,60.96 E12.7 | 93.98,62.23 95.25,60.96 E15.7 | 93.98,62.23 109.86,62.23 111.12,60.96 R3.1 111.76,60.33 113.03,60.33 113.03,57.78 111.76,56.52 R1.1 111.76,55.24 113.03,53.98 113.03,43.81 95.25,43.81 C15.2 | 21.59,53.34 24.77,56.52 24.77,59.69 30.48,59.69 31.75,60.96 34.29,60.96 E3.7 | 21.59,53.34 20.95,52.7 U$4.T2 19.68,52.07 v15.88,52.07 | C15.2 95.25,42.55 95.89,42.55 95.89,41.27 E14.7 97.16,40.01 98.42,38.73 98.42,23.5 95.25,23.5 C14.2 95.25,22.23 95.89,22.23 95.89,21.59 | E8.7 65.41,41.27 65.41,42.55 64.77,42.55 C9.2 | 80.64,41.91 80.64,42.55 80.01,42.55 C12.2 | 80.64,41.91 80.64,41.27 E11.7 | v70.48,40.64 71.75,41.91 80.64,41.91 | 80.64,41.91 93.34,41.91 94.61,43.18 C15.2 | E2.7 36.83,40.64 37.47,40.01 41.27,40.01 41.91,39.37 46.35,39.37 47.62,40.64 49.53,40.64 E5.7 50.8,41.27 49.53,42.55 C6.2 | 95.89,21.59 82.55,21.59 81.92,20.95 E10.7 80.64,20.95 80.64,22.23 80.01,22.23 C11.2 79.38,22.86 78.11,21.59 65.41,21.59 | C2.2 34.29,22.23 34.92,22.23 34.92,20.95 E1.7 36.83,20.32 37.47,19.68 41.27,19.68 41.91,19.05 v45.72,19.05 | E4.7 52.07,20.32 53.34,21.59 62.87,21.59 64.14,22.86 C8.2 64.77,22.23 65.41,22.23 65.41,21.59 | 65.41,21.59 65.41,20.95 E7.7 | 21.59,53.34 22.86,52.07 29.84,52.07 v30.48,51.44
  Bottom 0.381: v31.11,43.18 33.66,43.18 C3.2
H1  (via drill 0.61)
  Top 0.254: v15.88,22.86 13.97,22.86 U$1.H1 | v26.04,22.86 26.04,21.59 | 26.04,21.59 26.04,17.14 27.3,15.88 E1.10 | v55.24,33.02 56.52,31.75 56.52,14.61 57.78,13.34 E7.11 | 26.04,21.59 31.75,21.59 31.75,32.38 v31.11,33.02 | v47.62,38.1 48.9,36.83 48.9,34.92 50.16,33.66 E5.4
  Bottom 0.254: v15.88,22.86 19.68,22.86 U$4.H2 20.95,22.86 v26.04,22.86 | E14.11 87.63,33.02 86.36,31.75 76.2,31.75 74.93,30.48 E11.12 72.39,30.48 71.12,31.75 69.85,31.75 67.31,34.29 57.15,34.29 55.88,33.02 v55.24,33.02 52.07,33.02 E5.4 | v31.11,33.02 31.75,33.66 33.66,33.66 34.29,34.29 36.83,34.29 39.37,36.83 45.09,36.83 45.72,37.47 46.99,37.47 v47.62,38.1
H2  (via drill 0.61)
  Top 0.254: v24.13,24.13 24.13,23.5 25.4,22.23 25.4,16.51 26.04,15.88 v26.04,11.43 26.04,9.53 27.3,8.26 E1.13 | E13.4 95.25,12.7 91.44,16.51 81.92,16.51 81.92,15.88 E10.5 | v68.58,16.51 67.31,17.78 E7.6 | v40.01,13.34 41.91,15.24 E4.10
  Bottom 0.254: v24.13,24.13 18.41,24.13 U$4.H1 17.14,24.13 13.97,24.13 U$1.H2 | E4.10 44.45,15.24 45.09,15.88 48.9,15.88 49.53,16.51 63.5,16.51 64.77,17.78 E7.6 | v68.58,16.51 78.74,16.51 80.01,15.24 E10.5 | v26.04,11.43 38.1,11.43 v40.01,13.34
J1  (via drill 0.61)
  Top 0.254: 63.5,34.29 63.5,35.56 64.77,36.83 73.03,36.83 73.03,36.2 E11.10 | 63.5,34.29 63.5,28.57 60.33,25.4 60.33,24.13 59.05,24.13 58.42,23.5 58.42,20.95 E7.8 | U$1.J1 13.97,26.67 19.68,26.67 U$4.J2 | v55.88,34.29 63.5,34.29
  Bottom 0.254: E14.5 95.25,35.56 93.98,36.83 78.74,36.83 77.47,35.56 74.93,35.56 E11.10 | 33.02,26.67 34.29,25.4 E2.1 | 33.02,26.67 20.95,26.67 U$4.J2 | 33.02,26.67 48.9,26.67 48.9,33.66 50.16,34.92 E5.5 52.07,35.56 54.61,35.56 v55.88,34.29
J2  (via drill 0.61)
  Top 0.254: E8.3 66.67,29.84 67.94,28.57 67.94,27.94 69.22,26.67 76.2,26.67 77.47,27.94 78.74,27.94 78.74,20.32 80.64,18.41 E10.6 80.64,17.14 77.47,13.97 v77.47,2.54 | U$4.J1 18.41,27.94 20.95,27.94 22.86,26.04 22.86,17.14 v23.5,16.51 23.5,2.54 v19.05,2.54
  Bottom 0.254: E10.6 82.55,17.78 85.09,20.32 87.63,20.32 E13.8 | E1.12 26.67,10.16 26.04,10.16 23.5,12.7 v23.5,16.51 31.75,16.51 34.29,19.05 40.64,19.05 41.91,17.78 E4.9 | U$4.J1 17.14,27.3 13.97,27.3 U$1.J2 | v77.47,2.54 76.2,1.27 20.32,1.27 v19.05,2.54
K1  (via drill 0.61)
  Top 0.254: U$4.K2 19.68,29.21 13.97,29.21 U$1.K1 | v30.48,27.94 29.21,29.21 v25.4,29.21 | v52.7,31.75 52.7,36.2 51.44,37.47 E5.6 | v78.11,30.48 78.11,33.66 74.3,37.47 E11.9 | v47.62,29.21 48.9,27.94 48.9,27.3 49.53,26.67 v52.7,26.67
  Bottom 0.254: v30.48,27.94 34.29,27.94 E2.2 36.83,27.94 38.1,29.21 v47.62,29.21 | v25.4,29.21 20.95,29.21 U$4.K2 | E11.9 74.93,38.1 76.2,39.37 93.98,39.37 95.25,38.1 E14.6 | 69.85,29.21 72.39,26.67 71.12,25.4 67.31,25.4 E8.1 | 69.85,29.21 56.52,29.21 53.98,31.75 v52.7,31.75 v52.7,26.67 | v78.11,30.48 77.47,29.84 75.56,29.84 74.93,29.21 69.85,29.21
K2  (via drill 0.61)
  Top 0.254: v71.12,30.48 72.39,29.21 76.83,29.21 77.47,28.57 79.38,28.57 79.38,27.3 80.64,26.04 E11.1 | E2.3 36.2,29.84 37.47,28.57 37.47,26.04 42.55,20.95 E4.8 43.81,19.68 45.09,18.41 45.09,17.78 45.72,17.78 46.99,19.05 52.07,19.05 55.24,22.23 v55.24,31.75
  Bottom 0.254: E11.1 82.55,25.4 83.82,26.67 93.98,26.67 95.25,25.4 E14.1 | v71.12,30.48 69.85,30.48 67.31,33.02 E8.4 64.77,33.02 60.96,33.02 59.69,31.75 v55.24,31.75 | U$1.K2 13.97,29.84 17.14,29.84 U$4.K1 18.41,30.48 25.4,30.48 26.67,29.21 33.02,29.21 34.29,30.48 E2.3
L1  (via drill 0.61)
  Top 0.254: v69.22,27.94 69.85,28.57 v69.85,33.02 | v78.74,35.56 77.47,36.83 v77.47,40.64 | v69.22,43.18 73.03,43.18 73.03,41.27 E11.8 | U$4.L2 19.68,32.38 13.97,32.38 U$1.L1 | v47.62,43.18 47.62,44.45 46.99,45.09 46.99,45.72 48.26,46.99 49.53,45.72 E6.1 | v38.1,41.91 37.47,41.27 37.47,37.47 36.2,36.2 E2.5
  Bottom 0.254: v69.22,27.94 67.31,27.94 E8.2 | v69.85,33.02 71.12,34.29 77.47,34.29 v78.74,35.56 | v77.47,40.64 74.93,40.64 E11.8 | v69.22,43.18 68.58,43.18 67.31,44.45 59.05,44.45 58.42,43.81 53.98,43.81 52.07,45.72 E6.1 | U$4.L2 20.95,33.66 21.59,34.29 33.02,34.29 34.29,35.56 E2.5 | v47.62,43.18 46.35,41.91 v38.1,41.91
L2  (via drill 0.61)
  Top 0.254: v77.47,26.67 74.93,24.13 64.14,24.13 64.14,33.66 65.41,34.92 E8.5
  Bottom 0.254: U$1.L2 13.97,33.66 17.14,33.66 U$4.L1 18.41,33.66 18.41,31.75 32.38,31.75 33.66,33.02 34.29,33.02 E2.4 36.83,33.02 39.37,35.56 41.91,35.56 E5.10 44.45,35.56 45.09,35.56 46.35,36.83 59.69,36.83 60.96,35.56 64.77,35.56 E8.5 | E14.2 95.25,27.94 93.98,29.21 87.63,29.21 87,28.57 83.19,28.57 82.55,27.94 E11.2 80.01,27.94 78.74,26.67 v77.47,26.67
M1  (via drill 0.61)
  Top 0.254: U$4.M2 19.68,35.56 13.97,35.56 U$1.M1 | E15.12 88.27,51.44 88.27,52.07 78.74,52.07 74.93,48.26 E12.13 74.3,47.62 76.2,45.72 76.2,40.64 74.93,39.37 v62.87,39.37 | E6.2 51.44,47.62 53.98,45.09 v53.98,41.91 v53.98,30.48 53.98,29.21 49.53,29.21 48.9,29.84 48.9,30.48 v47.62,31.75 | v33.66,31.75 33.66,36.2 34.92,37.47 E2.6
  Bottom 0.254: U$4.M2 20.95,36.2 21.59,36.83 33.02,36.83 34.29,38.1 E2.6 | v53.98,30.48 55.88,28.57 56.52,28.57 57.15,27.94 E8.13 | v62.87,39.37 60.33,41.91 v53.98,41.91 | v33.66,31.75 v47.62,31.75
M2  (via drill 0.61)
  Top 0.254: E11.4 81.92,32.38 v83.82,30.48 v83.82,20.32 | v37.47,21.59 35.56,21.59 35.56,23.5 34.92,24.13 32.38,24.13 32.38,33.66 28.57,37.47 E2.9
  Bottom 0.254: v83.82,30.48 84.45,31.11 87,31.11 87.63,31.75 93.98,31.75 95.25,30.48 E14.3 | U$1.M2 13.97,36.2 17.14,36.2 U$4.M1 18.41,37.47 26.04,37.47 26.67,38.1 E2.9 29.21,38.1 31.11,38.1 32.38,39.37 40.64,39.37 41.91,38.1 E5.9 44.45,38.1 46.35,38.1 47.62,39.37 59.69,39.37 60.96,38.1 64.77,38.1 E8.6 | v83.82,20.32 82.55,19.05 46.99,19.05 44.45,21.59 v37.47,21.59
N1  (via drill 0.61)
  Top 0.254: U$4.N2 19.68,39.37 13.97,39.37 U$1.N1 | E12.12 74.93,50.8 78.74,54.61 88.27,54.61 88.27,53.98 E15.11 | v47.62,47.62 50.16,50.16 E6.3 | v60.33,26.67 60.33,28.57 59.05,29.84 E8.12 | v45.72,21.59 43.18,21.59 43.18,22.86 38.73,27.3 38.73,41.27 39.37,41.91 39.37,43.18 36.83,45.72 E3.1 34.29,45.72 33.02,44.45 33.02,41.27 v32.38,40.64 | v70.48,50.8 69.85,50.16 v69.85,48.26
  Bottom 0.254: v47.62,47.62 46.99,46.99 38.1,46.99 36.83,45.72 E3.1 | v60.33,26.67 56.52,26.67 51.44,21.59 v45.72,21.59 | v70.48,50.8 72.39,50.8 E12.12 | v69.85,48.26 68.58,46.99 55.88,46.99 52.07,50.8 E6.3 | v32.38,40.64 31.11,39.37 20.95,39.37 U$4.N2
N2  (via drill 0.61)
  Top 0.254: v60.96,31.75 59.69,33.02 E8.11 | v68.58,30.48 68.58,33.02 69.85,34.29 76.2,34.29 76.2,31.11 78.11,29.21 79.38,29.21 79.38,33.66 80.64,34.92 E11.5 80.64,36.2 78.74,38.1 v78.74,46.35 | v69.85,46.99 68.58,48.26 68.58,56.52 69.22,57.15 69.22,57.78 67.31,59.69 60.96,59.69 60.96,60.96 59.69,62.23 48.26,62.23 v48.26,58.42 | v26.04,57.15 26.04,42.55 27.3,41.27 E2.8
  Bottom 0.254: v60.96,31.75 67.31,31.75 v68.58,30.48 | E14.4 95.25,33.02 93.98,34.29 83.82,34.29 82.55,35.56 E11.5 | U$1.N2 13.97,40.01 17.14,40.01 U$4.N1 18.41,40.64 26.67,40.64 E2.8 29.21,40.64 31.11,40.64 32.38,41.91 36.83,41.91 38.1,40.64 41.91,40.64 E5.8 | v78.74,46.35 78.11,46.99 v69.85,46.99 | v48.26,58.42 46.99,57.15 v26.04,57.15
P1  (via drill 0.61)
  Top 0.254: v69.22,44.45 71.75,46.99 71.75,53.98 73.03,55.24 E12.10 74.93,55.88 77.47,55.88 78.74,57.15 90.81,57.15 92.08,55.88 95.25,55.88 E15.5 | U$4.P2 19.68,41.91 13.97,41.91 U$1.P1 | v31.11,41.91 32.38,43.18 32.38,45.09 34.92,47.62 E3.2 36.83,48.26 38.1,46.99 38.73,46.99 38.73,47.62 39.37,48.26 39.37,52.07 41.91,54.61 50.16,54.61 50.16,53.98 E6.4 52.07,53.34 53.34,52.07 54.61,53.34 54.61,54.61 60.96,54.61 v62.23,55.88
  Bottom 0.254: v69.22,44.45 68.58,44.45 67.31,45.72 E9.1 | v31.11,41.91 20.95,41.91 U$4.P2 | v62.23,55.88 63.5,55.88 64.77,54.61 67.31,54.61 67.94,55.24 71.75,55.24 72.39,55.88 E12.10
P2  (via drill 0.61)
  Top 0.254: v60.96,36.83 59.69,35.56 E8.10 57.78,36.2 55.24,38.73 v55.24,45.09 | E14.8 87.63,40.64 84.45,40.64 84.45,40.01 82.55,38.1 E11.6 | v24.77,49.53 21.59,46.35 21.59,45.09 20.32,43.81 18.41,43.81 U$4.P1
  Bottom 0.254: v60.96,36.83 77.47,36.83 78.74,38.1 80.01,38.1 E11.6 | U$4.P1 17.14,42.55 13.97,42.55 U$1.P2 | v24.77,49.53 29.21,49.53 29.84,50.16 33.66,50.16 34.29,50.8 E3.3 36.83,50.8 40.64,50.8 42.55,48.9 E6.13 43.81,48.9 47.62,48.9 49.53,46.99 53.34,46.99 v55.24,45.09
R1  (via drill 0.61)
  Top 0.254: v67.94,57.15 67.94,50.16 66.67,48.9 E9.2 65.41,48.9 63.5,50.8 v63.5,53.34 | v77.47,57.15 74.3,57.15 74.3,57.78 E12.9 | v40.64,55.88 41.91,57.15 45.72,57.15 45.72,55.88 49.53,55.88 E6.5 51.44,55.24 v53.34,53.34 | 19.05,45.09 13.97,45.09 U$1.R1 | 19.05,45.09 19.68,45.09 U$4.R2 | 19.05,45.09 19.05,55.88 20.95,55.88 21.59,56.52 21.59,59.69 30.48,59.69 34.29,55.88 E3.5
  Bottom 0.254: v67.94,57.15 69.22,58.42 72.39,58.42 E12.9 | v77.47,57.15 93.98,57.15 95.25,58.42 E15.6 | v40.64,55.88 36.83,55.88 E3.5 | v63.5,53.34 62.87,53.98 60.33,53.98 59.69,54.61 57.15,54.61 55.88,53.34 v53.34,53.34
R2  (via drill 0.61)
  Top 0.254: v55.24,46.35 56.52,45.09 56.52,40.01 57.78,38.73 E8.9 59.05,38.73 61.59,41.27 61.59,41.91 65.41,41.91 v69.22,45.72 | v40.64,44.45 41.27,45.09 41.27,48.9 42.55,50.16 E6.12
  Bottom 0.254: U$1.R2 13.97,46.35 17.14,46.35 U$4.R1 18.41,46.35 18.41,44.45 v40.64,44.45 | E15.1 95.25,45.72 93.98,46.99 83.82,46.99 82.55,45.72 E12.1 80.01,45.72 79.38,45.09 75.56,45.09 74.93,44.45 70.48,44.45 v69.22,45.72 | E3.4 36.83,53.34 39.37,53.34 41.91,50.8 E6.12 44.45,50.8 45.72,49.53 52.07,49.53 v55.24,46.35
S1  (via drill 0.61)
  Top 0.254: v15.88,48.26 13.97,48.26 U$1.S1 | 39.37,60.96 40.64,62.23 46.99,62.23 46.99,58.42 48.26,57.15 49.53,58.42 E6.6 | 39.37,60.96 36.83,58.42 E3.6 | v63.5,58.42 63.5,55.88 62.23,54.61 62.23,52.07 59.05,48.9 E9.13 | v33.02,48.26 34.29,49.53 38.1,49.53 38.1,57.15 39.37,58.42 39.37,60.96
  Bottom 0.254: v15.88,48.26 19.68,48.26 U$4.S2 20.95,47.62 21.59,46.99 31.75,46.99 v33.02,48.26 | 64.14,59.05 64.77,59.69 71.12,59.69 72.39,60.96 E12.8 | 64.14,59.05 v63.5,58.42 | 64.14,59.05 61.59,59.05 59.69,57.15 57.15,57.15 55.88,55.88 54.61,55.88 52.07,58.42 E6.6
S2  (via drill 0.61)
  Top 0.254: v60.96,48.26 60.96,41.91 59.69,40.64 E8.8 | v40.64,49.53 40.64,50.8 42.55,52.7 E6.11 43.81,52.7 45.09,51.44 45.09,45.72 v46.35,44.45
  Bottom 0.254: v60.96,48.26 62.23,49.53 78.74,49.53 | 78.74,49.53 80.01,48.26 E12.2 | 78.74,49.53 93.98,49.53 95.25,48.26 E15.2 | U$1.S2 13.97,49.53 17.14,49.53 U$4.S1 18.41,49.53 20.95,49.53 22.23,48.26 26.67,48.26 E3.13 29.21,48.26 30.48,49.53 v40.64,49.53 | v46.35,44.45 50.16,44.45 53.98,40.64 57.15,40.64 E8.8
T2  (via drill 0.61)
  Top 0.254: v33.02,46.99 31.75,48.26 31.75,52.7 29.84,52.7 28.57,51.44 E3.12 | v38.1,48.26 38.73,48.9 38.73,52.7 41.91,55.88 E6.10
  Bottom 0.254: E3.12 26.67,50.8 14.61,50.8 13.97,51.44 U$1.T2 13.97,52.7 14.61,53.34 17.14,53.34 U$4.T1 | 78.74,52.07 68.58,52.07 67.31,50.8 E9.3 64.77,50.8 60.96,50.8 59.69,52.07 48.26,52.07 44.45,55.88 E6.10 | 78.74,52.07 80.01,53.34 E12.4 | 78.74,52.07 93.98,52.07 95.25,50.8 E15.3 | v33.02,46.99 36.83,46.99 v38.1,48.26
U1  (via drill 0.61)
  Top 0.254: v15.88,54.61 13.97,54.61 U$1.U1 | v24.77,54.61 24.77,53.34 23.5,52.07 21.59,52.07 21.59,53.34 20.95,53.98 U$4.U2 | v46.99,52.07 52.07,52.07 52.7,51.44 52.7,50.8 57.15,50.8 E9.12 59.69,50.8 v60.96,52.07 | v70.48,53.34 70.48,59.69 82.55,59.69 83.19,60.33 83.19,62.23 97.79,62.23 98.42,61.59 98.42,59.69 101.6,56.52 R1.2
  Bottom 0.254: R2.1 101.6,53.98 101.6,55.24 R1.2 | v15.88,54.61 19.68,54.61 U$4.U2 | 25.4,54.61 26.67,55.88 E3.10 | v24.77,54.61 25.4,54.61 | v46.99,52.07 44.45,54.61 25.4,54.61 | v70.48,53.34 69.85,52.7 67.94,52.7 67.31,52.07 v60.96,52.07
U2  (via drill 0.61)
  Top 0.254: v23.5,58.42 26.67,58.42 E3.9 28.57,57.78 29.84,56.52 29.84,54.61 36.83,54.61 37.47,55.24 37.47,57.78 v38.1,58.42 | v60.96,55.88 59.69,57.15 v55.88,57.15
  Bottom 0.254: 78.74,54.61 68.58,54.61 67.31,53.34 E9.4 64.77,53.34 63.5,54.61 62.23,54.61 v60.96,55.88 | 78.74,54.61 80.01,55.88 E12.5 | 78.74,54.61 93.98,54.61 95.25,53.34 E15.4 | U$1.U2 13.97,55.88 17.14,55.88 U$4.U1 17.78,56.52 19.68,58.42 v23.5,58.42 | v38.1,58.42 41.91,58.42 E6.9 44.45,58.42 45.72,59.69 53.34,59.69 v55.88,57.15
V1  (via drill 0.61)
  Top 0.254: U$1.V1 13.97,57.78 13.97,57.15 19.68,57.15 U$4.V2 20.95,57.78 20.95,60.33 v21.59,60.96 | v23.5,53.34 22.23,54.61 v22.23,55.88
  Bottom 0.254: 75.56,59.69 99.69,59.69 100.97,60.96 R3.2 101.6,60.33 101.6,59.05 R4.1 | 75.56,59.69 72.39,59.69 71.75,59.05 67.94,59.05 67.31,58.42 E9.6 | v23.5,53.34 26.67,53.34 E3.11 | v22.23,55.88 21.59,56.52 20.95,56.52 U$4.V2 | 75.56,59.69 75.56,62.23 22.86,62.23 v21.59,60.96
V2  (via drill 0.61)
  Top 0.254: E15.8 87.63,60.96 84.45,57.78 81.92,57.78 E12.6 | v32.38,59.69 31.11,60.96 29.21,60.96 E3.8 | v61.59,57.78 59.69,59.69 52.7,59.69 52.7,57.78 52.07,57.15 49.53,57.15 48.9,56.52 46.35,56.52 46.35,57.78 43.81,60.33 E6.8
  Bottom 0.254: E12.6 80.01,58.42 77.47,58.42 76.2,57.15 72.39,57.15 71.12,55.88 67.31,55.88 E9.5 64.77,55.88 62.87,57.78 v61.59,57.78 | U$1.V2 13.97,57.78 17.14,57.78 U$4.V1 18.41,59.05 20.95,59.05 22.23,60.33 26.04,60.33 26.67,60.96 E3.8 | v32.38,59.69 40.64,59.69 41.91,60.96 E6.8
VCC  (via drill 0.61)
  Top 0.381: E3.14 28.57,45.09 28.57,44.45 29.21,43.81 C3.1 29.21,42.55 29.84,41.91 29.84,40.01 29.21,39.37 24.13,39.37 24.13,27.94 26.67,25.4 E2.14 | 45.09,41.91 44.45,42.55 C6.1 | 45.09,41.91 45.09,27.3 43.81,26.04 E5.14 | E9.14 59.05,45.09 59.69,44.45 59.69,43.81 C9.1 | E12.14 74.3,45.09 74.93,44.45 74.93,43.81 C12.1 | E14.14 89.53,26.04 90.81,27.3 90.81,43.18 C15.1 | 45.09,41.91 52.7,41.91 v52.7,43.18 | C13.1 90.81,2.54 94.61,6.35 98.42,6.35 98.42,20.95 97.79,21.59 90.17,21.59 90.17,22.23 C14.1
  Bottom 0.381: C13.1 90.17,3.17 88.9,4.45 E13.14 87.63,5.08 86.36,3.81 74.3,3.81 | 74.3,3.81 74.3,3.17 74.93,3.17 C10.1 | 74.3,3.81 74.3,4.45 E10.14 72.39,5.08 71.12,3.81 59.05,3.81 | 59.05,3.81 58.42,4.45 E7.14 57.15,5.08 55.88,3.81 43.81,3.81 | 59.05,3.81 59.69,3.17 C7.1 | 43.81,3.81 43.18,4.45 E4.14 41.91,5.08 40.64,3.81 28.57,3.81 | 43.81,3.81 44.45,3.17 C4.1 | 28.57,3.81 27.94,4.45 E1.14 26.67,5.08 18.41,5.08 U$4.A1 17.14,4.45 14.61,4.45 U$1.A2 | 28.57,3.81 29.21,3.17 C1.1 | C6.1 44.45,43.81 43.18,45.09 E6.14 | E2.14 27.94,24.77 29.21,23.5 C2.1 29.84,22.86 31.11,24.13 43.81,24.13 | 43.81,24.13 43.18,24.77 E5.14 | 43.81,24.13 44.45,23.5 C5.1 | C14.1 90.17,23.5 88.9,24.77 E14.14 87.63,25.4 86.36,24.13 74.3,24.13 | E8.14 58.42,24.77 59.69,23.5 C8.1 60.33,22.86 61.59,24.13 74.3,24.13 | 74.3,24.13 74.3,23.5 74.93,23.5 C11.1 | 74.3,24.13 74.3,24.77 E11.14 | R4.2 111.12,58.42 110.49,58.42 110.49,55.24 111.76,53.98 R2.2 111.12,53.34 102.23,44.45 89.53,44.45 | 89.53,44.45 88.9,45.09 E15.14 87.63,45.72 86.36,44.45 76.83,44.45 75.56,43.18 C12.1 74.3,43.18 71.12,43.18 67.31,39.37 64.77,39.37 63.5,40.64 62.87,40.64 60.33,43.18 C9.1 59.05,43.18 v52.7,43.18 | 89.53,44.45 90.17,43.81 C15.1

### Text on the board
Bottom: VRS | M111/M113/M115/M117/M119 Replacement
tNames: M111 | M113 | M115 | M117 | M119 | Fill Only One Row. | M113/M117/M119: Use Resistors. | M111/M115: Remove Resistors. | M111/M113/M115/M117/M119 Replacement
